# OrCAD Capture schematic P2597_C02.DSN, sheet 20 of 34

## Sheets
20 14_HDMI: size Custom
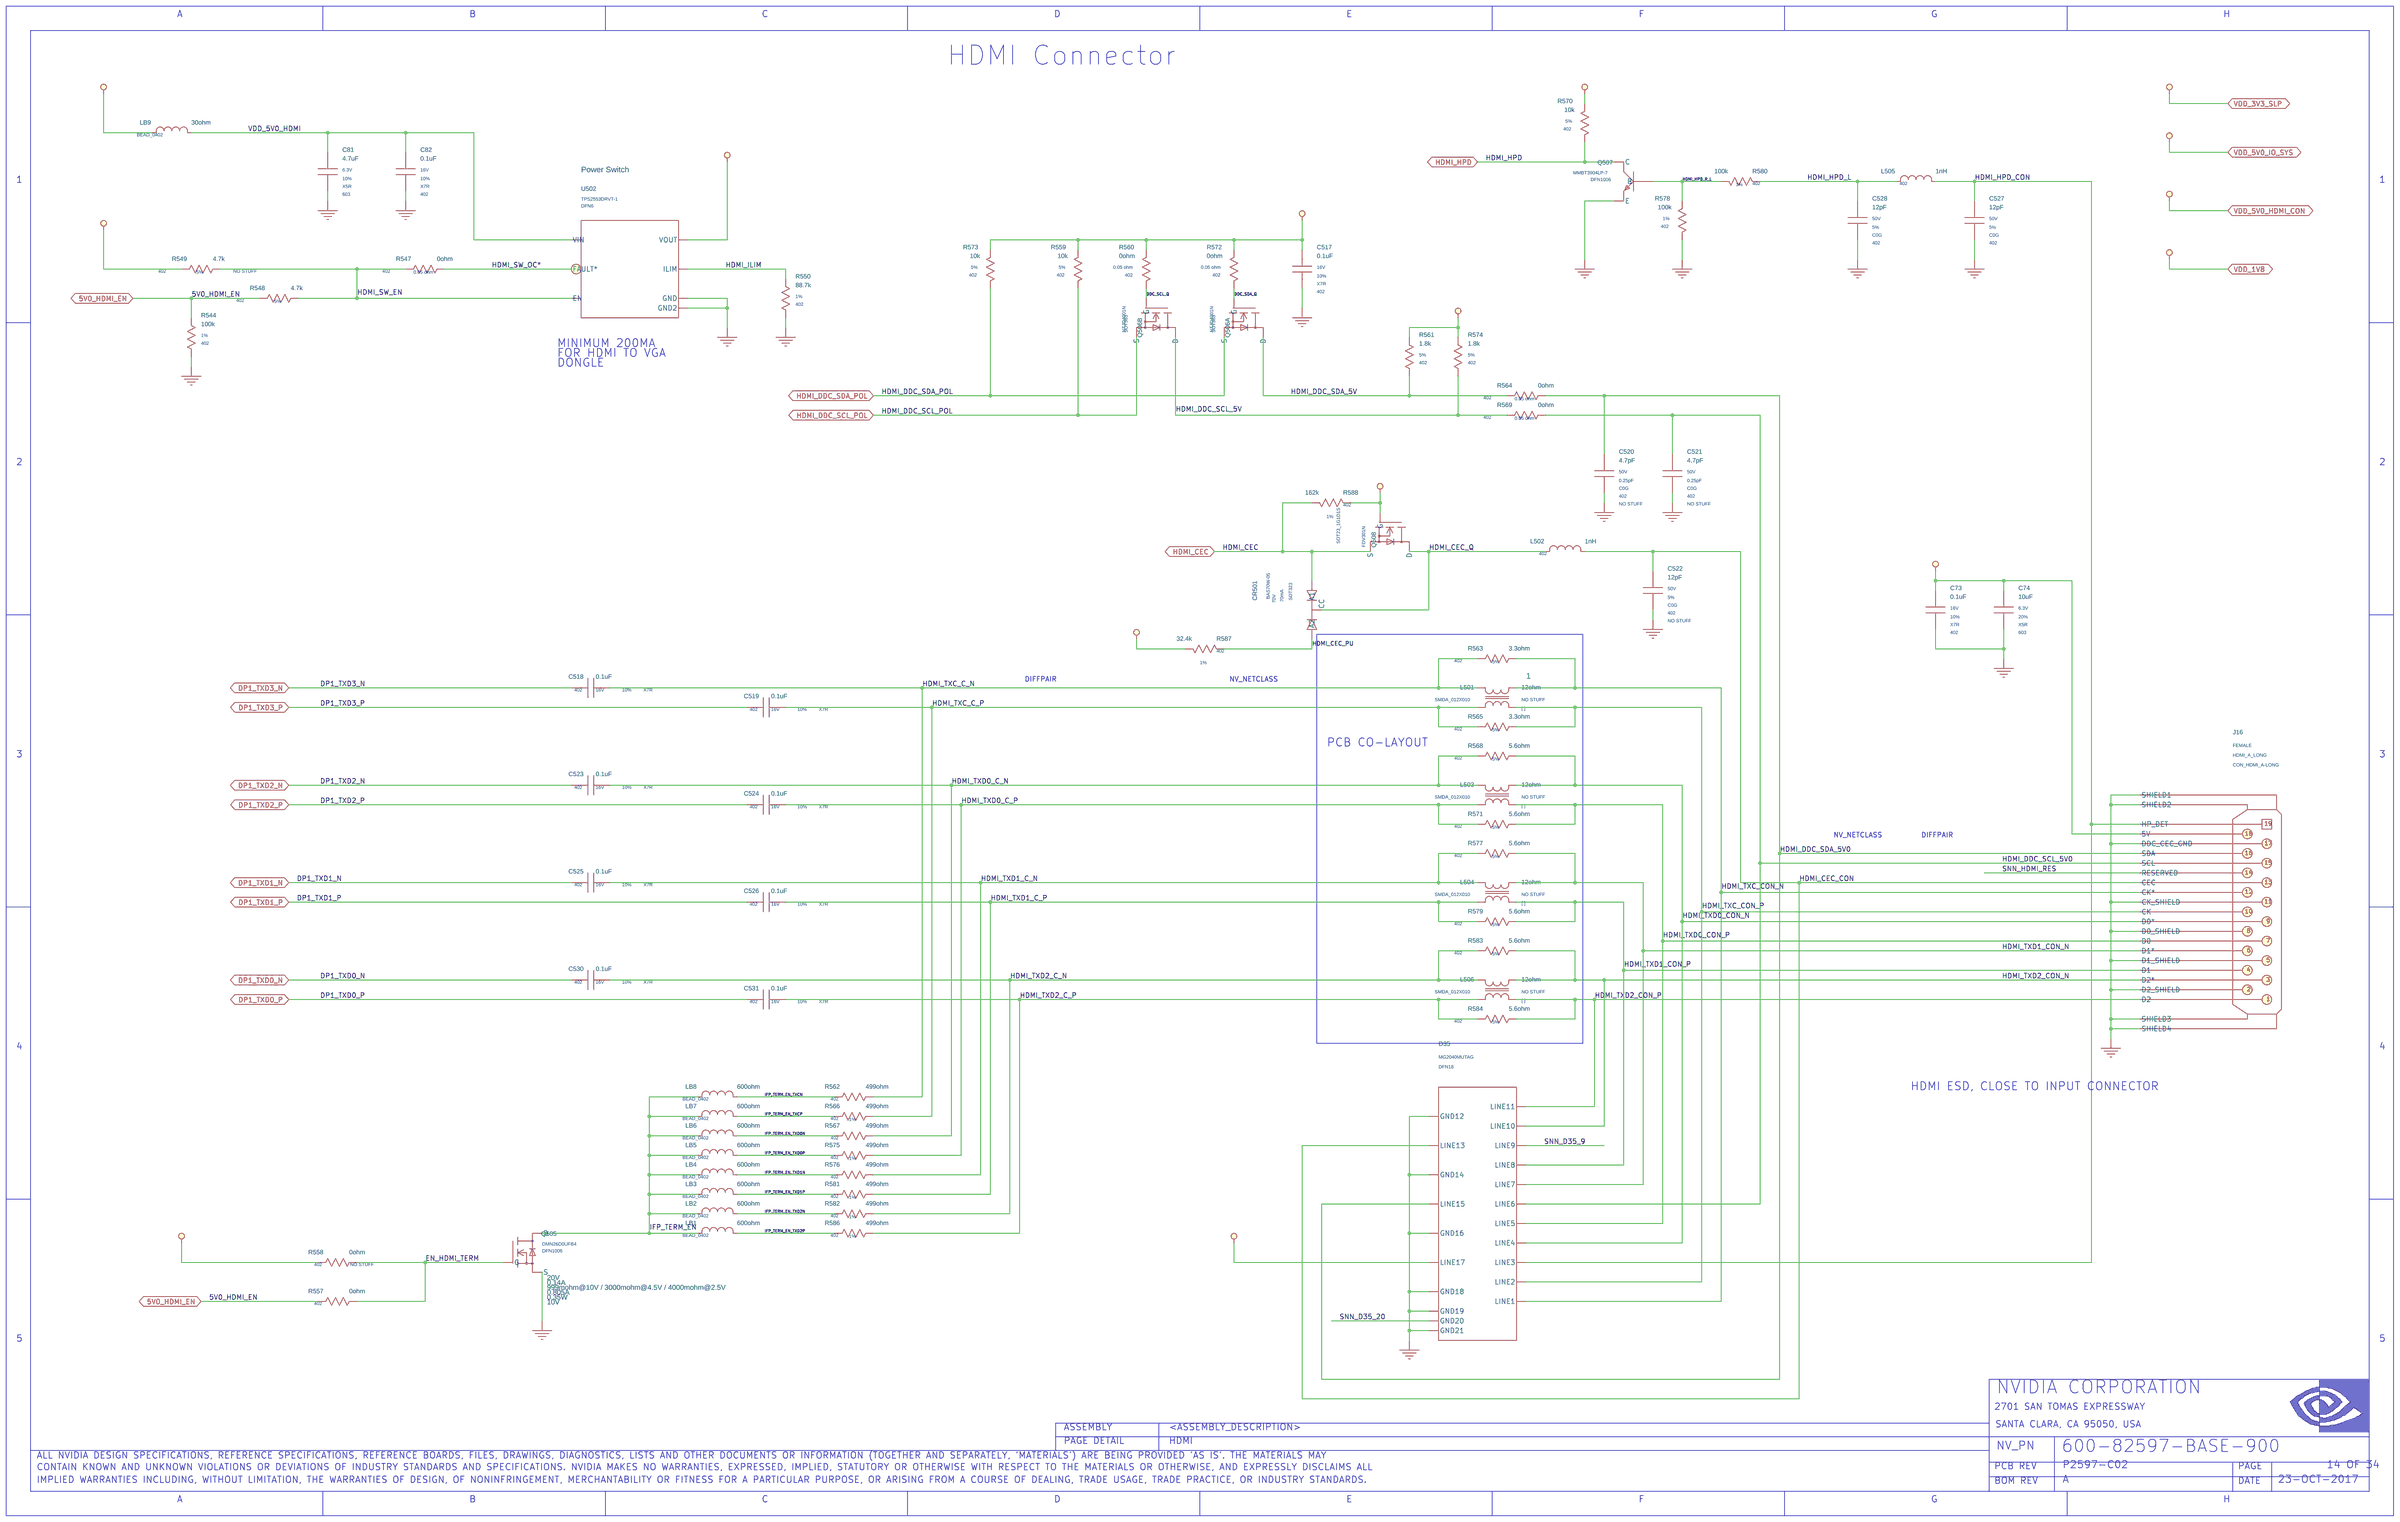
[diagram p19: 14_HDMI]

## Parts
C73  0.1uF  [402]
C74  10uF  [603]
C81  4.7uF  [603]
C82  0.1uF  [402]
C517  0.1uF  [402]
C518  0.1uF  [402]
C519  0.1uF  [402]
C520  4.7pF  [402]
C521  4.7pF  [402]
C522  12pF  [402]
C523  0.1uF  [402]
C524  0.1uF  [402]
C525  0.1uF  [402]
C526  0.1uF  [402]
C527  12pF  [402]
C528  12pF  [402]
C530  0.1uF  [402]
C531  0.1uF  [402]
CR501  D_3PIN_CC  [SOT323]
D35  D_ESD  [DFN18_P050_055X015_3XT006X005]
J16  CON_HDMI  [CON_HDMI_019_SMD_RA_F_C]
L501  12ohm  [IND_NONRKO_SMD_012X010]
L502  1nH  [IND_SMD_0402]
L503  12ohm  [IND_NONRKO_SMD_012X010]
L504  12ohm  [IND_NONRKO_SMD_012X010]
L505  1nH  [IND_SMD_0402]
L506  12ohm  [IND_NONRKO_SMD_012X010]
LB1  600ohm  [IND_SMD_0402]
LB2  600ohm  [IND_SMD_0402]
LB3  600ohm  [IND_SMD_0402]
LB4  600ohm  [IND_SMD_0402]
LB5  600ohm  [IND_SMD_0402]
LB6  600ohm  [IND_SMD_0402]
LB7  600ohm  [IND_SMD_0402]
LB8  600ohm  [IND_SMD_0402]
LB9  30ohm  [IND_SMD_0402]
Q505  Q_FET_N_ENH  [DFET_003_SMD_010X006_B]
Q506  Q_FET_N_ENH  [SC70_6]  (sections A,B)
Q507  Q_NPN  [DFET_003_SMD_010X006_B]
Q508  Q_FET_N_ENH  [SOT23]
R544  100k  [402]
R547  0ohm  [402]
R548  4.7k  [402]
R549  4.7k  [402]
R550  88.7k  [402]
R557  0ohm  [402]
R558  0ohm  [402]
R559  10k  [402]
R560  0ohm  [402]
R561  1.8k  [402]
R562  499ohm  [402]
R563  3.3ohm  [402]
R564  0ohm  [402]
R565  3.3ohm  [402]
R566  499ohm  [402]
R567  499ohm  [402]
R568  5.6ohm  [402]
R569  0ohm  [402]
R570  10k  [402]
R571  5.6ohm  [402]
R572  0ohm  [402]
R573  10k  [402]
R574  1.8k  [402]
R575  499ohm  [402]
R576  499ohm  [402]
R577  5.6ohm  [402]
R578  100k  [402]
R579  5.6ohm  [402]
R580  100k  [402]
R581  499ohm  [402]
R582  499ohm  [402]
R583  5.6ohm  [402]
R584  5.6ohm  [402]
R586  499ohm  [402]
R587  32.4k  [402]
R588  162k  [402]
U502  U_POWER_SW  [DFN06_P065_020X020_T016X010]

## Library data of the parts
C73 = C: ASSEMBLY: HDMI; CDS_LIB: discrete; CDS_PART_NAME: C_0402-0.1UF,X7R,10%,16V,036-0014-000; CDS_PHYS_PART_NAME: C_0402-0.1UF,X7R,10%,16V,036-0014-000-0.1UF,036-0014-000; CDS_SEC: 1; DEVICE_TYPENAME: C_0402-01UFX7R1016V036-0014-000-01UF036-0014-000; DRAWING: @P2597_C02_LIB.P2597_C02(SCH_1):PAGE14; ESL: N/A; ESR: N/A; MAT: X7R; MAX_VOLTAGE: 16V; NV_PN: 036-0014-000; PATH: I332; PHYS_PAGE: 14; ROT: 0; SEC: 1; SIGNAL_MODEL: nv_cap; TOL: 10%; VER: 1; XY: (-2250,4500)
C74 = C: ASSEMBLY: HDMI; CDS_LIB: discrete; CDS_PART_NAME: C_0603-10UF,X5R,20%,6.3V,039-0135-000; CDS_PHYS_PART_NAME: C_0603-10UF,X5R,20%,6.3V,039-0135-000-039-0135-000,10UF; CDS_SEC: 1; DEVICE_TYPENAME: C_0603-10UFX5R2063V039-0135-000-039-0135-00010UF; DRAWING: @P2597_C02_LIB.P2597_C02(SCH_1):PAGE14; ESL: N/A; ESR: N/A; MAT: X5R; MAX_VOLTAGE: 6.3V; NV_PN: 039-0135-000; PATH: I340; PHYS_PAGE: 14; ROT: 0; SEC: 1; SIGNAL_MODEL: nv_cap; TOL: 20%; VER: 1; XY: (-1900,4500)
C81 = C: ASSEMBLY: HDMI; CDS_LIB: discrete; CDS_PART_NAME: C_0603-4.7UF,X5R,10%,6.3V,039-0037-000; CDS_PHYS_PART_NAME: C_0603-4.7UF,X5R,10%,6.3V,039-0037-000-039-0037-000,4.7UF; CDS_SEC: 1; DEVICE_TYPENAME: C_0603-47UFX5R1063V039-0037-000-039-0037-00047UF; DRAWING: @P2597_C02_LIB.P2597_C02(SCH_1):PAGE14; MAT: X5R; MAX_VOLTAGE: 6.3V; NV_PN: 039-0037-000; PATH: I266; PHYS_PAGE: 14; ROT: 0; SEC: 1; SIGNAL_MODEL: nv_cap; TOL: 10%; VER: 1; XY: (-10500,6750)
C82 = C: ASSEMBLY: HDMI; CDS_LIB: discrete; CDS_PART_NAME: C_0402-0.1UF,X7R,10%,16V,036-0014-000; CDS_PHYS_PART_NAME: C_0402-0.1UF,X7R,10%,16V,036-0014-000-0.1UF,036-0014-000; CDS_SEC: 1; DEVICE_TYPENAME: C_0402-01UFX7R1016V036-0014-000-01UF036-0014-000; DRAWING: @P2597_C02_LIB.P2597_C02(SCH_1):PAGE14; ESL: N/A; ESR: N/A; MAT: X7R; MAX_VOLTAGE: 16V; NV_PN: 036-0014-000; PATH: I271; PHYS_PAGE: 14; ROT: 0; SEC: 1; SIGNAL_MODEL: nv_cap; TOL: 10%; VER: 1; XY: (-10100,6750)
C517 = C: ASSEMBLY: HDMI; CDS_LIB: discrete; CDS_PART_NAME: C_0402-0.1UF,X7R,10%,16V,036-0014-000; CDS_PHYS_PART_NAME: C_0402-0.1UF,X7R,10%,16V,036-0014-000-0.1UF,036-0014-000; CDS_SEC: 1; DEVICE_TYPENAME: C_0402-01UFX7R1016V036-0014-000-01UF036-0014-000; DRAWING: @P2597_C02_LIB.P2597_C02(SCH_1):PAGE14; ESL: N/A; ESR: N/A; MAT: X7R; MAX_VOLTAGE: 16V; NV_PN: 036-0014-000; PATH: I315; PHYS_PAGE: 14; ROT: 0; SEC: 1; SIGNAL_MODEL: nv_cap; TOL: 10%; VER: 1; XY: (-5500,6250)
C518 = C#1: ASSEMBLY: IO_HDMI; CDS_LIB: discrete; CDS_PART_NAME: C_0402-0.1UF,X7R,10%,16V,036-0014-000; CDS_PHYS_PART_NAME: C_0402-0.1UF,X7R,10%,16V,036-0014-000-0.1UF,036-0014-000; CDS_SEC: 1; CHIPS_PART_NAME: C; DEVICE_TYPENAME: C_0402-01UFX7R1016V036-0014-000-01UF036-0014-000; DRAWING: @P2597_C02_LIB.P2597_C02(SCH_1):PAGE14; MAT: X7R; MAX_VOLTAGE: 16V; NO_XNET: 1; NV_PN: 036-0014-000; PATH: I259; PHYS_PAGE: 14; ROT: 0; SEC: 1; SIGNAL_MODEL: nv_cap; TOL: 10%; VER: 2; XY: (-9150,4100)
C519 = C#1: ASSEMBLY: IO_HDMI; CDS_LIB: discrete; CDS_PART_NAME: C_0402-0.1UF,X7R,10%,16V,036-0014-000; CDS_PHYS_PART_NAME: C_0402-0.1UF,X7R,10%,16V,036-0014-000-0.1UF,036-0014-000; CDS_SEC: 1; CHIPS_PART_NAME: C; DEVICE_TYPENAME: C_0402-01UFX7R1016V036-0014-000-01UF036-0014-000; DRAWING: @P2597_C02_LIB.P2597_C02(SCH_1):PAGE14; MAT: X7R; MAX_VOLTAGE: 16V; NO_XNET: 1; NV_PN: 036-0014-000; PATH: I260; PHYS_PAGE: 14; ROT: 0; SEC: 1; SIGNAL_MODEL: nv_cap; TOL: 10%; VER: 2; XY: (-8250,4000)
C520 = C: ASSEMBLY: HDMI; CDS_LIB: discrete; CDS_PART_NAME: C_0402-4.7PF,C0G,0.25PF,50V,035-0031-000; CDS_PHYS_PART_NAME: C_0402-4.7PF,C0G,0.25PF,50V,035-0031-000-035-0031-000,4.7PF; CDS_SEC: 1; DEVICE_TYPENAME: C_0402-47PFC0G025PF50V035-0031-000-035-0031-00047PF; DRAWING: @P2597_C02_LIB.P2597_C02(SCH_1):PAGE14; MAT: C0G; MAX_VOLTAGE: 50V; NV_PN: 035-0031-000; PATH: I342; PHYS_PAGE: 14; ROT: 0; SEC: 1; SIGNAL_MODEL: nv_cap; SKU: NO STUFF; TOL: 0.25pF; VER: 1; XY: (-3950,5200)
C521 = C: ASSEMBLY: HDMI; CDS_LIB: discrete; CDS_PART_NAME: C_0402-4.7PF,C0G,0.25PF,50V,035-0031-000; CDS_PHYS_PART_NAME: C_0402-4.7PF,C0G,0.25PF,50V,035-0031-000-035-0031-000,4.7PF; CDS_SEC: 1; DEVICE_TYPENAME: C_0402-47PFC0G025PF50V035-0031-000-035-0031-00047PF; DRAWING: @P2597_C02_LIB.P2597_C02(SCH_1):PAGE14; MAT: C0G; MAX_VOLTAGE: 50V; NV_PN: 035-0031-000; PATH: I344; PHYS_PAGE: 14; ROT: 0; SEC: 1; SIGNAL_MODEL: nv_cap; SKU: NO STUFF; TOL: 0.25pF; VER: 1; XY: (-3600,5200)
C522 = C: ASSEMBLY: HDMI; CDS_LIB: discrete; CDS_PART_NAME: C_0402-12PF,C0G,5%,50V,035-0014-000; CDS_PHYS_PART_NAME: C_0402-12PF,C0G,5%,50V,035-0014-000-035-0014-000,12PF; CDS_SEC: 1; DEVICE_TYPENAME: C_0402-12PFC0G550V035-0014-000-035-0014-00012PF; DRAWING: @P2597_C02_LIB.P2597_C02(SCH_1):PAGE14; ESL: N/A; ESR: N/A; MAT: C0G; MAX_VOLTAGE: 50V; NV_PN: 035-0014-000; PATH: I330; PHYS_PAGE: 14; ROT: 0; SEC: 1; SIGNAL_MODEL: nv_cap; SKU: NO STUFF; TOL: 5%; VER: 1; XY: (-3700,4600)
C523 = C#1: ASSEMBLY: IO_HDMI; CDS_LIB: discrete; CDS_PART_NAME: C_0402-0.1UF,X7R,10%,16V,036-0014-000; CDS_PHYS_PART_NAME: C_0402-0.1UF,X7R,10%,16V,036-0014-000-0.1UF,036-0014-000; CDS_SEC: 1; CHIPS_PART_NAME: C; DEVICE_TYPENAME: C_0402-01UFX7R1016V036-0014-000-01UF036-0014-000; DRAWING: @P2597_C02_LIB.P2597_C02(SCH_1):PAGE14; MAT: X7R; MAX_VOLTAGE: 16V; NO_XNET: 1; NV_PN: 036-0014-000; PATH: I258; PHYS_PAGE: 14; ROT: 0; SEC: 1; SIGNAL_MODEL: nv_cap; TOL: 10%; VER: 2; XY: (-9150,3600)
C524 = C#1: ASSEMBLY: IO_HDMI; CDS_LIB: discrete; CDS_PART_NAME: C_0402-0.1UF,X7R,10%,16V,036-0014-000; CDS_PHYS_PART_NAME: C_0402-0.1UF,X7R,10%,16V,036-0014-000-0.1UF,036-0014-000; CDS_SEC: 1; CHIPS_PART_NAME: C; DEVICE_TYPENAME: C_0402-01UFX7R1016V036-0014-000-01UF036-0014-000; DRAWING: @P2597_C02_LIB.P2597_C02(SCH_1):PAGE14; MAT: X7R; MAX_VOLTAGE: 16V; NO_XNET: 1; NV_PN: 036-0014-000; PATH: I255; PHYS_PAGE: 14; ROT: 0; SEC: 1; SIGNAL_MODEL: nv_cap; TOL: 10%; VER: 2; XY: (-8250,3500)
C525 = C#1: ASSEMBLY: IO_HDMI; CDS_LIB: discrete; CDS_PART_NAME: C_0402-0.1UF,X7R,10%,16V,036-0014-000; CDS_PHYS_PART_NAME: C_0402-0.1UF,X7R,10%,16V,036-0014-000-0.1UF,036-0014-000; CDS_SEC: 1; CHIPS_PART_NAME: C; DEVICE_TYPENAME: C_0402-01UFX7R1016V036-0014-000-01UF036-0014-000; DRAWING: @P2597_C02_LIB.P2597_C02(SCH_1):PAGE14; MAT: X7R; MAX_VOLTAGE: 16V; NO_XNET: 1; NV_PN: 036-0014-000; PATH: I254; PHYS_PAGE: 14; ROT: 0; SEC: 1; SIGNAL_MODEL: nv_cap; TOL: 10%; VER: 2; XY: (-9150,3100)
C526 = C#1: ASSEMBLY: IO_HDMI; CDS_LIB: discrete; CDS_PART_NAME: C_0402-0.1UF,X7R,10%,16V,036-0014-000; CDS_PHYS_PART_NAME: C_0402-0.1UF,X7R,10%,16V,036-0014-000-0.1UF,036-0014-000; CDS_SEC: 1; CHIPS_PART_NAME: C; DEVICE_TYPENAME: C_0402-01UFX7R1016V036-0014-000-01UF036-0014-000; DRAWING: @P2597_C02_LIB.P2597_C02(SCH_1):PAGE14; MAT: X7R; MAX_VOLTAGE: 16V; NO_XNET: 1; NV_PN: 036-0014-000; PATH: I256; PHYS_PAGE: 14; ROT: 0; SEC: 1; SIGNAL_MODEL: nv_cap; TOL: 10%; VER: 2; XY: (-8250,3000)
C527 = C: ASSEMBLY: HDMI; CDS_LIB: discrete; CDS_PART_NAME: C_0402-12PF,C0G,5%,50V,035-0014-000; CDS_PHYS_PART_NAME: C_0402-12PF,C0G,5%,50V,035-0014-000-035-0014-000,12PF; CDS_SEC: 1; DEVICE_TYPENAME: C_0402-12PFC0G550V035-0014-000-035-0014-00012PF; DRAWING: @P2597_C02_LIB.P2597_C02(SCH_1):PAGE14; ESL: N/A; ESR: N/A; MAT: C0G; MAX_VOLTAGE: 50V; NV_PN: 035-0014-000; PATH: I357; PHYS_PAGE: 14; ROT: 0; SEC: 1; SIGNAL_MODEL: nv_cap; TOL: 5%; VER: 1; XY: (-2050,6500)
C528 = C: ASSEMBLY: HDMI; CDS_LIB: discrete; CDS_PART_NAME: C_0402-12PF,C0G,5%,50V,035-0014-000; CDS_PHYS_PART_NAME: C_0402-12PF,C0G,5%,50V,035-0014-000-035-0014-000,12PF; CDS_SEC: 1; DEVICE_TYPENAME: C_0402-12PFC0G550V035-0014-000-035-0014-00012PF; DRAWING: @P2597_C02_LIB.P2597_C02(SCH_1):PAGE14; ESL: N/A; ESR: N/A; MAT: C0G; MAX_VOLTAGE: 50V; NV_PN: 035-0014-000; PATH: I350; PHYS_PAGE: 14; ROT: 0; SEC: 1; SIGNAL_MODEL: nv_cap; TOL: 5%; VER: 1; XY: (-2650,6500)
C530 = C#1: ASSEMBLY: IO_HDMI; CDS_LIB: discrete; CDS_PART_NAME: C_0402-0.1UF,X7R,10%,16V,036-0014-000; CDS_PHYS_PART_NAME: C_0402-0.1UF,X7R,10%,16V,036-0014-000-0.1UF,036-0014-000; CDS_SEC: 1; CHIPS_PART_NAME: C; DEVICE_TYPENAME: C_0402-01UFX7R1016V036-0014-000-01UF036-0014-000; DRAWING: @P2597_C02_LIB.P2597_C02(SCH_1):PAGE14; MAT: X7R; MAX_VOLTAGE: 16V; NO_XNET: 1; NV_PN: 036-0014-000; PATH: I253; PHYS_PAGE: 14; ROT: 0; SEC: 1; SIGNAL_MODEL: nv_cap; TOL: 10%; VER: 2; XY: (-9150,2600)
C531 = C#1: ASSEMBLY: IO_HDMI; CDS_LIB: discrete; CDS_PART_NAME: C_0402-0.1UF,X7R,10%,16V,036-0014-000; CDS_PHYS_PART_NAME: C_0402-0.1UF,X7R,10%,16V,036-0014-000-0.1UF,036-0014-000; CDS_SEC: 1; CHIPS_PART_NAME: C; DEVICE_TYPENAME: C_0402-01UFX7R1016V036-0014-000-01UF036-0014-000; DRAWING: @P2597_C02_LIB.P2597_C02(SCH_1):PAGE14; MAT: X7R; MAX_VOLTAGE: 16V; NO_XNET: 1; NV_PN: 036-0014-000; PATH: I257; PHYS_PAGE: 14; ROT: 0; SEC: 1; SIGNAL_MODEL: nv_cap; TOL: 10%; VER: 2; XY: (-8250,2500)
CR501 = D_3PIN_CC#1: ASSEMBLY: HDMI; CDS_LIB: discrete; CDS_PART_NAME: D_3PIN_CC_SOT323-BAS70W-05,1 PAIR - COMMON CATHODE,70V,0.1A,1V@15MA,70MA,091-0023-000; CDS_PHYS_PART_NAME: D_3PIN_CC_SOT323-BAS70W-05,1 PAIR - COMMON CATHODE,70V,0.1A,1V@15MA,70MA,091-0023-000-091-0023-000; CDS_SEC: 1; CONFIGURATION: 1 Pair - Common Cathode; CONTINUOUS_CURRENT: 70mA; DEVICE_TYPENAME: D_3PIN_CC_SOT323-BAS70W-051PAIR-COMMONCATHODE70V01A1V15MA70MA091-0023-000-091-0023-000; DRAWING: @P2597_C02_LIB.P2597_C02(SCH_1):PAGE14; FORWARD_VOLTAGE: 1V@15mA; MAX_CURRENT: 0.1A; MAX_VOLTAGE: 70V; NV_NAME: BAS70W-05; NV_PN: 091-0023-000; PATH: I291; PHYS_PAGE: 14; ROT: 1; SEC: 1; VER: 4; XY: (-5450,4500)
D35 = D_ESD#2: ASSEMBLY: HDMI; BREAKDOWN_VOLTAGE_MIN_TYP: 5.5V; CAPACITANCE_MAX_TYP: 0.42pF; CDS_LIB: discrete; CDS_PART_NAME: D_ESD_DFN18-MG2040MUTAG,OTHER,UNI-DIRECTIONAL,5V,1UA,5.5V,11.4V@8A,0.42PF,091-0080-000; CDS_PHYS_PART_NAME: D_ESD_DFN18-MG2040MUTAG,OTHER,UNI-DIRECTIONAL,5V,1UA,5.5V,11.4V@8A,0.42PF,091-0080-000-091-0080-000; CDS_SEC: 1; CLAMPING_VOLTAGE: 11.4V@8A; CONFIGURATION: Other; DEVICE_TYPENAME: D_ESD_DFN18-MG2040MUTAGOTHERUNI-DIRECTIONAL5V1UA55V114V8A042PF091-0080-000-091-0080-000; DRAWING: @P2597_C02_LIB.P2597_C02(SCH_1):PAGE14; MAX_REVERSE_LEAKAGE_CURRENT: 1uA; MAX_REVERSE_VOLTAGE: 5V; NV_NAME: MG2040MUTAG; NV_PN: 091-0080-000; PACK_TYPE: DFN18; PATH: I381; PHYS_PAGE: 14; POLARITY: Uni-Directional; ROT: 0; SEC: 1; SEC_TYPE: DFN18; VER: 7; XY: (-4600,1450)
J16 = CON_HDMI: ANGLE: 90; ASSEMBLY: HDMI; CDS_LIB: electro_mechanic; CDS_PART_NAME: CON_HDMI_HDMI_A_LONG-CON_HDMI_A-LONG,FEMALE,0.5MM,90,YES,N/A,N/A,YES,YES,N/A,N/A,080-0420-000; CDS_PHYS_PART_NAME: CON_HDMI_HDMI_A_LONG-CON_HDMI_A-LONG,FEMALE,0.5MM,90,YES,N/A,N/A,YES,YES,N/A,N/A,080-0420-000-080-0420-000; CDS_SEC: 1; DEVICE_TYPENAME: CON_HDMI_HDMI_A_LONG-CON_HDMI_A-LONGFEMALE05MM90YESNANAYESYESNANA080-0420-000-080-0420-000; DRAWING: @P2597_C02_LIB.P2597_C02(SCH_1):PAGE14; EMI_GROUND_TAB: YES; GENDER: FEMALE; LATCHING: N/A; MAX_CURRENT: N/A; MAX_VOLTAGE: N/A; NV_NAME: CON_HDMI_A-LONG; NV_PN: 080-0420-000; PACK_TYPE: HDMI_A_LONG; PATH: I338; PHYS_PAGE: 14; PITCH: 0.5MM; REFLOW: YES; ROT: 0; SEC: 1; SEC_TYPE: HDMI_A_LONG; SHIELDED: YES; SHROUDED: N/A; VER: 1; XY: (-600,2950)
L501 = L_CMF_4P: ASSEMBLY: HDMI; CDS_LIB: discrete; CDS_PART_NAME: L_CMF_4P_SMDA_012X010-12OHM,[ ],[ ],0.1A,0.7OHM,[ ],102-0015-000; CDS_PHYS_PART_NAME: L_CMF_4P_SMDA_012X010-12OHM,[ ],[ ],0.1A,0.7OHM,[ ],102-0015-000-102-0015-000,12OHM; CDS_SEC: 1; DC_RESISTANCE: 0.7ohm; DEVICE_TYPENAME: L_CMF_4P_SMDA_012X010-12OHM01A07OHM102-0015-000-102-0015-00012OHM; DRAWING: @P2597_C02_LIB.P2597_C02(SCH_1):PAGE14; MAT: [ ]; MAX_CURRENT: 0.1A; NO_XNET_CONNECTION: 1; NV_NAME: [ ]; NV_PN: 102-0015-000; PACK_TYPE: SMDA_012X010; PATH: I301; PHYS_PAGE: 14; PLACEMENT_NOTE: CoLayout with R563, R565; ROT: 0; SEC: 1; SEC_TYPE: SMDA_012X010; SIGNAL_MODEL: nv_ind_cmf_4p; SKU: NO STUFF; TOL: [ ]; VER: 1; XY: (-4500,4050)
L502 = L: ACOUSTIC_MARGIN: [ ]; ASSEMBLY: HDMI; CDS_LIB: discrete; CDS_PART_NAME: L_0402-1NH,MULTI-LAYER,30%,0.4A,0.4A,0.07OHM,8@100MHZ,10GHZ,[ ],130-1041-000; CDS_PHYS_PART_NAME: L_0402-1NH,MULTI-LAYER,30%,0.4A,0.4A,0.07OHM,8@100MHZ,10GHZ,[ ],130-1041-000-130-1041-000,1NH; CDS_SEC: 1; CONTINUOUS_CURRENT: 0.4A; DC_RESISTANCE: 0.07ohm; DEVICE_TYPENAME: L_0402-1NHMULTI-LAYER3004A04A007OHM8100MHZ10GHZ130-1041-000-130-1041-0001NH; DRAWING: @P2597_C02_LIB.P2597_C02(SCH_1):PAGE14; MAT: multi-layer; MAX_CURRENT: 0.4A; NV_PN: 130-1041-000; PACK_TYPE: 402; PATH: I319; PHYS_PAGE: 14; Q: 8@100MHz; ROT: 0; SEC: 1; SELF_RESONANCE_FREQ: 10GHz; SIGNAL_MODEL: nv_ind; TOL: 30%; VER: 1; XY: (-4150,4800)
L503 = L_CMF_4P: ASSEMBLY: HDMI; CDS_LIB: discrete; CDS_PART_NAME: L_CMF_4P_SMDA_012X010-12OHM,[ ],[ ],0.1A,0.7OHM,[ ],102-0015-000; CDS_PHYS_PART_NAME: L_CMF_4P_SMDA_012X010-12OHM,[ ],[ ],0.1A,0.7OHM,[ ],102-0015-000-102-0015-000,12OHM; CDS_SEC: 1; DC_RESISTANCE: 0.7ohm; DEVICE_TYPENAME: L_CMF_4P_SMDA_012X010-12OHM01A07OHM102-0015-000-102-0015-00012OHM; DRAWING: @P2597_C02_LIB.P2597_C02(SCH_1):PAGE14; MAT: [ ]; MAX_CURRENT: 0.1A; NV_NAME: [ ]; NV_PN: 102-0015-000; PACK_TYPE: SMDA_012X010; PATH: I298; PHYS_PAGE: 14; PLACEMENT_NOTE: CoLayout with R568, R571; ROT: 0; SEC: 1; SEC_TYPE: SMDA_012X010; SIGNAL_MODEL: nv_ind_cmf_4p; SKU: NO STUFF; TOL: [ ]; VER: 1; XY: (-4500,3550)
L504 = L_CMF_4P: ASSEMBLY: HDMI; CDS_LIB: discrete; CDS_PART_NAME: L_CMF_4P_SMDA_012X010-12OHM,[ ],[ ],0.1A,0.7OHM,[ ],102-0015-000; CDS_PHYS_PART_NAME: L_CMF_4P_SMDA_012X010-12OHM,[ ],[ ],0.1A,0.7OHM,[ ],102-0015-000-102-0015-000,12OHM; CDS_SEC: 1; DC_RESISTANCE: 0.7ohm; DEVICE_TYPENAME: L_CMF_4P_SMDA_012X010-12OHM01A07OHM102-0015-000-102-0015-00012OHM; DRAWING: @P2597_C02_LIB.P2597_C02(SCH_1):PAGE14; MAT: [ ]; MAX_CURRENT: 0.1A; NV_NAME: [ ]; NV_PN: 102-0015-000; PACK_TYPE: SMDA_012X010; PATH: I295; PHYS_PAGE: 14; PLACEMENT_NOTE: CoLayout with R577, R579; ROT: 0; SEC: 1; SEC_TYPE: SMDA_012X010; SIGNAL_MODEL: nv_ind_cmf_4p; SKU: NO STUFF; TOL: [ ]; VER: 1; XY: (-4500,3050)
L505 = L: ACOUSTIC_MARGIN: [ ]; ASSEMBLY: HDMI; CDS_LIB: discrete; CDS_PART_NAME: L_0402-1NH,MULTI-LAYER,30%,0.4A,0.4A,0.07OHM,8@100MHZ,10GHZ,[ ],130-1041-000; CDS_PHYS_PART_NAME: L_0402-1NH,MULTI-LAYER,30%,0.4A,0.4A,0.07OHM,8@100MHZ,10GHZ,[ ],130-1041-000-130-1041-000,1NH; CDS_SEC: 1; CONTINUOUS_CURRENT: 0.4A; DC_RESISTANCE: 0.07ohm; DEVICE_TYPENAME: L_0402-1NHMULTI-LAYER3004A04A007OHM8100MHZ10GHZ130-1041-000-130-1041-0001NH; DRAWING: @P2597_C02_LIB.P2597_C02(SCH_1):PAGE14; MAT: multi-layer; MAX_CURRENT: 0.4A; NV_PN: 130-1041-000; PACK_TYPE: 402; PATH: I355; PHYS_PAGE: 14; Q: 8@100MHz; ROT: 0; SEC: 1; SELF_RESONANCE_FREQ: 10GHz; SIGNAL_MODEL: nv_ind; TOL: 30%; VER: 1; XY: (-2350,6700)
L506 = L_CMF_4P: ASSEMBLY: HDMI; CDS_LIB: discrete; CDS_PART_NAME: L_CMF_4P_SMDA_012X010-12OHM,[ ],[ ],0.1A,0.7OHM,[ ],102-0015-000; CDS_PHYS_PART_NAME: L_CMF_4P_SMDA_012X010-12OHM,[ ],[ ],0.1A,0.7OHM,[ ],102-0015-000-102-0015-000,12OHM; CDS_SEC: 1; DC_RESISTANCE: 0.7ohm; DEVICE_TYPENAME: L_CMF_4P_SMDA_012X010-12OHM01A07OHM102-0015-000-102-0015-00012OHM; DRAWING: @P2597_C02_LIB.P2597_C02(SCH_1):PAGE14; MAT: [ ]; MAX_CURRENT: 0.1A; NV_NAME: [ ]; NV_PN: 102-0015-000; PACK_TYPE: SMDA_012X010; PATH: I293; PHYS_PAGE: 14; PLACEMENT_NOTE: CoLayout with R583, R584; ROT: 0; SEC: 1; SEC_TYPE: SMDA_012X010; SIGNAL_MODEL: nv_ind_cmf_4p; SKU: NO STUFF; TOL: [ ]; VER: 1; XY: (-4500,2550)
LB1 = L: ACOUSTIC_MARGIN: N/A; ASSEMBLY: HDMI; CDS_LIB: discrete; CDS_PART_NAME: L_BEAD_0402-600OHM,FERRITE,25%,0.5A,0.5A,0.39OHM,[ ],N/A,N/A,100-0183-000; CDS_PHYS_PART_NAME: L_BEAD_0402-600OHM,FERRITE,25%,0.5A,0.5A,0.39OHM,[ ],N/A,N/A,100-0183-000-100-0183-000,600OHM; CDS_SEC: 1; CONTINUOUS_CURRENT: 0.5A; DC_RESISTANCE: 0.39ohm; DEVICE_TYPENAME: L_BEAD_0402-600OHMFERRITE2505A05A039OHMNANA100-0183-000-100-0183-000600OHM; DRAWING: @P2597_C02_LIB.P2597_C02(SCH_1):PAGE14; MAT: Ferrite; MAX_CURRENT: 0.5A; NV_PN: 100-0183-000; PACK_TYPE: BEAD_0402; PATH: I363; PHYS_PAGE: 14; Q: [ ]; ROT: 0; SEC: 1; SELF_RESONANCE_FREQ: N/A; SIGNAL_MODEL: nv_ind_noxnet; TOL: 25%; VER: 1; XY: (-8500,1300)
LB2 = L: ACOUSTIC_MARGIN: N/A; ASSEMBLY: HDMI; CDS_LIB: discrete; CDS_PART_NAME: L_BEAD_0402-600OHM,FERRITE,25%,0.5A,0.5A,0.39OHM,[ ],N/A,N/A,100-0183-000; CDS_PHYS_PART_NAME: L_BEAD_0402-600OHM,FERRITE,25%,0.5A,0.5A,0.39OHM,[ ],N/A,N/A,100-0183-000-100-0183-000,600OHM; CDS_SEC: 1; CONTINUOUS_CURRENT: 0.5A; DC_RESISTANCE: 0.39ohm; DEVICE_TYPENAME: L_BEAD_0402-600OHMFERRITE2505A05A039OHMNANA100-0183-000-100-0183-000600OHM; DRAWING: @P2597_C02_LIB.P2597_C02(SCH_1):PAGE14; MAT: Ferrite; MAX_CURRENT: 0.5A; NV_PN: 100-0183-000; PACK_TYPE: BEAD_0402; PATH: I364; PHYS_PAGE: 14; Q: [ ]; ROT: 0; SEC: 1; SELF_RESONANCE_FREQ: N/A; SIGNAL_MODEL: nv_ind_noxnet; TOL: 25%; VER: 1; XY: (-8500,1400)
LB3 = L: ACOUSTIC_MARGIN: N/A; ASSEMBLY: HDMI; CDS_LIB: discrete; CDS_PART_NAME: L_BEAD_0402-600OHM,FERRITE,25%,0.5A,0.5A,0.39OHM,[ ],N/A,N/A,100-0183-000; CDS_PHYS_PART_NAME: L_BEAD_0402-600OHM,FERRITE,25%,0.5A,0.5A,0.39OHM,[ ],N/A,N/A,100-0183-000-100-0183-000,600OHM; CDS_SEC: 1; CONTINUOUS_CURRENT: 0.5A; DC_RESISTANCE: 0.39ohm; DEVICE_TYPENAME: L_BEAD_0402-600OHMFERRITE2505A05A039OHMNANA100-0183-000-100-0183-000600OHM; DRAWING: @P2597_C02_LIB.P2597_C02(SCH_1):PAGE14; MAT: Ferrite; MAX_CURRENT: 0.5A; NV_PN: 100-0183-000; PACK_TYPE: BEAD_0402; PATH: I240; PHYS_PAGE: 14; Q: [ ]; ROT: 0; SEC: 1; SELF_RESONANCE_FREQ: N/A; SIGNAL_MODEL: nv_ind_noxnet; TOL: 25%; VER: 1; XY: (-8500,1500)
LB4 = L: ACOUSTIC_MARGIN: N/A; ASSEMBLY: HDMI; CDS_LIB: discrete; CDS_PART_NAME: L_BEAD_0402-600OHM,FERRITE,25%,0.5A,0.5A,0.39OHM,[ ],N/A,N/A,100-0183-000; CDS_PHYS_PART_NAME: L_BEAD_0402-600OHM,FERRITE,25%,0.5A,0.5A,0.39OHM,[ ],N/A,N/A,100-0183-000-100-0183-000,600OHM; CDS_SEC: 1; CONTINUOUS_CURRENT: 0.5A; DC_RESISTANCE: 0.39ohm; DEVICE_TYPENAME: L_BEAD_0402-600OHMFERRITE2505A05A039OHMNANA100-0183-000-100-0183-000600OHM; DRAWING: @P2597_C02_LIB.P2597_C02(SCH_1):PAGE14; MAT: Ferrite; MAX_CURRENT: 0.5A; NV_PN: 100-0183-000; PACK_TYPE: BEAD_0402; PATH: I241; PHYS_PAGE: 14; Q: [ ]; ROT: 0; SEC: 1; SELF_RESONANCE_FREQ: N/A; SIGNAL_MODEL: nv_ind_noxnet; TOL: 25%; VER: 1; XY: (-8500,1600)
LB5 = L: ACOUSTIC_MARGIN: N/A; ASSEMBLY: HDMI; CDS_LIB: discrete; CDS_PART_NAME: L_BEAD_0402-600OHM,FERRITE,25%,0.5A,0.5A,0.39OHM,[ ],N/A,N/A,100-0183-000; CDS_PHYS_PART_NAME: L_BEAD_0402-600OHM,FERRITE,25%,0.5A,0.5A,0.39OHM,[ ],N/A,N/A,100-0183-000-100-0183-000,600OHM; CDS_SEC: 1; CONTINUOUS_CURRENT: 0.5A; DC_RESISTANCE: 0.39ohm; DEVICE_TYPENAME: L_BEAD_0402-600OHMFERRITE2505A05A039OHMNANA100-0183-000-100-0183-000600OHM; DRAWING: @P2597_C02_LIB.P2597_C02(SCH_1):PAGE14; MAT: Ferrite; MAX_CURRENT: 0.5A; NV_PN: 100-0183-000; PACK_TYPE: BEAD_0402; PATH: I242; PHYS_PAGE: 14; Q: [ ]; ROT: 0; SEC: 1; SELF_RESONANCE_FREQ: N/A; SIGNAL_MODEL: nv_ind_noxnet; TOL: 25%; VER: 1; XY: (-8500,1700)
LB6 = L: ACOUSTIC_MARGIN: N/A; ASSEMBLY: HDMI; CDS_LIB: discrete; CDS_PART_NAME: L_BEAD_0402-600OHM,FERRITE,25%,0.5A,0.5A,0.39OHM,[ ],N/A,N/A,100-0183-000; CDS_PHYS_PART_NAME: L_BEAD_0402-600OHM,FERRITE,25%,0.5A,0.5A,0.39OHM,[ ],N/A,N/A,100-0183-000-100-0183-000,600OHM; CDS_SEC: 1; CONTINUOUS_CURRENT: 0.5A; DC_RESISTANCE: 0.39ohm; DEVICE_TYPENAME: L_BEAD_0402-600OHMFERRITE2505A05A039OHMNANA100-0183-000-100-0183-000600OHM; DRAWING: @P2597_C02_LIB.P2597_C02(SCH_1):PAGE14; MAT: Ferrite; MAX_CURRENT: 0.5A; NV_PN: 100-0183-000; PACK_TYPE: BEAD_0402; PATH: I243; PHYS_PAGE: 14; Q: [ ]; ROT: 0; SEC: 1; SELF_RESONANCE_FREQ: N/A; SIGNAL_MODEL: nv_ind_noxnet; TOL: 25%; VER: 1; XY: (-8500,1800)
LB7 = L: ACOUSTIC_MARGIN: N/A; ASSEMBLY: HDMI; CDS_LIB: discrete; CDS_PART_NAME: L_BEAD_0402-600OHM,FERRITE,25%,0.5A,0.5A,0.39OHM,[ ],N/A,N/A,100-0183-000; CDS_PHYS_PART_NAME: L_BEAD_0402-600OHM,FERRITE,25%,0.5A,0.5A,0.39OHM,[ ],N/A,N/A,100-0183-000-100-0183-000,600OHM; CDS_SEC: 1; CONTINUOUS_CURRENT: 0.5A; DC_RESISTANCE: 0.39ohm; DEVICE_TYPENAME: L_BEAD_0402-600OHMFERRITE2505A05A039OHMNANA100-0183-000-100-0183-000600OHM; DRAWING: @P2597_C02_LIB.P2597_C02(SCH_1):PAGE14; MAT: Ferrite; MAX_CURRENT: 0.5A; NV_PN: 100-0183-000; PACK_TYPE: BEAD_0402; PATH: I244; PHYS_PAGE: 14; Q: [ ]; ROT: 0; SEC: 1; SELF_RESONANCE_FREQ: N/A; SIGNAL_MODEL: nv_ind_noxnet; TOL: 25%; VER: 1; XY: (-8500,1900)
LB8 = L: ACOUSTIC_MARGIN: N/A; ASSEMBLY: HDMI; CDS_LIB: discrete; CDS_PART_NAME: L_BEAD_0402-600OHM,FERRITE,25%,0.5A,0.5A,0.39OHM,[ ],N/A,N/A,100-0183-000; CDS_PHYS_PART_NAME: L_BEAD_0402-600OHM,FERRITE,25%,0.5A,0.5A,0.39OHM,[ ],N/A,N/A,100-0183-000-100-0183-000,600OHM; CDS_SEC: 1; CONTINUOUS_CURRENT: 0.5A; DC_RESISTANCE: 0.39ohm; DEVICE_TYPENAME: L_BEAD_0402-600OHMFERRITE2505A05A039OHMNANA100-0183-000-100-0183-000600OHM; DRAWING: @P2597_C02_LIB.P2597_C02(SCH_1):PAGE14; MAT: Ferrite; MAX_CURRENT: 0.5A; NV_PN: 100-0183-000; PACK_TYPE: BEAD_0402; PATH: I245; PHYS_PAGE: 14; Q: [ ]; ROT: 0; SEC: 1; SELF_RESONANCE_FREQ: N/A; SIGNAL_MODEL: nv_ind_noxnet; TOL: 25%; VER: 1; XY: (-8500,2000)
LB9 = L: ACOUSTIC_MARGIN: N/A; ASSEMBLY: HDMI; CDS_LIB: discrete; CDS_PART_NAME: L_BEAD_0402-30OHM,FERRITE,25%,[ ],2A,0.1OHM,[ ],N/A,N/A,100-0165-000; CDS_PHYS_PART_NAME: L_BEAD_0402-30OHM,FERRITE,25%,[ ],2A,0.1OHM,[ ],N/A,N/A,100-0165-000-100-0165-000,30OHM; CDS_SEC: 1; CONTINUOUS_CURRENT: [ ]; DC_RESISTANCE: 0.1ohm; DEVICE_TYPENAME: L_BEAD_0402-30OHMFERRITE252A01OHMNANA100-0165-000-100-0165-00030OHM; DRAWING: @P2597_C02_LIB.P2597_C02(SCH_1):PAGE14; MAT: Ferrite; MAX_CURRENT: 2A; NV_PN: 100-0165-000; PACK_TYPE: BEAD_0402; PATH: I264; PHYS_PAGE: 14; Q: [ ]; ROT: 0; SEC: 1; SELF_RESONANCE_FREQ: N/A; SIGNAL_MODEL: nv_ind_noxnet; TOL: 25%; VER: 1; XY: (-11300,6950)
Q505 = Q_FET_N_ENH#2: ASSEMBLY: HDMI; CDS_LIB: discrete; CDS_PART_NAME: Q_FET_N_ENH_DFN1006-DMN26D0UFB4,20V,999MOHM@10V / 3000MOHM@4.5V / 4000MOHM@2.5V,0.14A,0.805A,10V,0.35W,999NC@10V / 999NC@4.5V A; CDS_PHYS_PART_NAME: Q_FET_N_ENH_DFN1006-DMN26D0UFB4,20V,999MOHM@10V / 3000MOHM@4.5V / 4000MOHM@2.5V,0.14A,0.805A,10V,0.35W,999NC@10V / 999NC@4.5V B; CDS_SEC: 1; CONTINUOUS_CURRENT: 0.14A; CaptureCellPackProp: Q_FET_N_ENH__sym_2##2; DEVICE_TYPENAME: Q_FET_N_ENH_DFN1006-DMN26D0UFB420V999MOHM10V3000MOHM45V4000MOHM25V014A0805A10V035W999NC10V999NC45VB; DRAWING: @P2597_C02_LIB.P2597_C02(SCH_1):PAGE14; MAX_CURRENT: 0.805A; MAX_VOLTAGE: 20V; MAX_WATTAGE: 0.35W; NV_NAME: DMN26D0UFB4; NV_PN: 300-0868-000; PACK_TYPE: DFN1006; PATH: I362; PHYS_PAGE: 14; Q_G: 999nC@10V / 999nC@4.5V / 999nC@2.5V; ROT: 0; R_DS_ON: 999mohm@10V / 3000mohm@4.5V / 4000mohm@2.5V; SEC: 1; VER: 2; V_BE_GS: 10V; XY: (-9500,1200)
Q506 = Q_FET_N_ENH#1: ASSEMBLY: HDMI; CDS_LIB: discrete; CDS_PART_NAME: Q_FET_N_ENH_SOT363-NTJD4001N,30V,1500MOHM@10V / 1500MOHM@4.5V / 1500MOHM@2.5V,0.25A,0.25A,20V,0.272W,[ ]@10V / [ ]@4.5V / [ ]@A; CDS_PHYS_PART_NAME: Q_FET_N_ENH_SOT363-NTJD4001N,30V,1500MOHM@10V / 1500MOHM@4.5V / 1500MOHM@2.5V,0.25A,0.25A,20V,0.272W,[ ]@10V / [ ]@4.5V / [ ]@B; CDS_SEC: 1; CONTINUOUS_CURRENT: 0.25A; CaptureCellPackProp: Q_FET_N_ENH__sym_2##1; DEVICE_TYPENAME: Q_FET_N_ENH_SOT363-NTJD4001N30V1500MOHM10V1500MOHM45V1500MOHM25V025A025A20V0272W10V45VB; DRAWING: @P2597_C02_LIB.P2597_C02(SCH_1):PAGE14; MAX_CURRENT: 0.25A; MAX_VOLTAGE: 30V; MAX_WATTAGE: 0.272W; NV_NAME: NTJD4001N; NV_PN: 300-0402-000; PACK_TYPE: SOT363; PATH: I312; PHYS_PAGE: 14; Q_G: [ ]@10V / [ ]@4.5V / [ ]@2.5V; ROT: 5; R_DS_ON: 1500mohm@10V / 1500mohm@4.5V / 1500mohm@2.5V; SEC: 1; SEC_TYPE: SOT363; VER: 2; V_BE_GS: 20V; XY: (-5800,6000)
Q507 = Q_NPN: ASSEMBLY: HDMI; CDS_LIB: discrete; CDS_PART_NAME: Q_NPN_DFN1006-MMBT3904LP-7,40V,0.3V,0.2A,9999A,6V,0.25W,300-0869-000; CDS_PHYS_PART_NAME: Q_NPN_DFN1006-MMBT3904LP-7,40V,0.3V,0.2A,9999A,6V,0.25W,300-0869-000-300-0869-000; CDS_SEC: 1; CONTINUOUS_CURRENT: 0.2A; DEVICE_TYPENAME: Q_NPN_DFN1006-MMBT3904LP-740V03V02A9999A6V025W300-0869-000-300-0869-000; DRAWING: @P2597_C02_LIB.P2597_C02(SCH_1):PAGE14; MAX_CURRENT: 9999A; MAX_VOLTAGE: 40V; MAX_WATTAGE: 0.25W; NV_NAME: MMBT3904LP-7; NV_PN: 300-0869-000; PACK_TYPE: DFN1006; PATH: I352; PHYS_PAGE: 14; ROT: 2; SEC: 1; VER: 1; V_BE_GS: 6V; V_CE_SAT: 0.3V; XY: (-3800,6700)
Q508 = Q_FET_N_ENH#2: ASSEMBLY: HDMI; CDS_LIB: discrete; CDS_PART_NAME: Q_FET_N_ENH_SOT23_1G1D1S-FDV301N,25V,-1000MOHM@10V / 4000MOHM@4.5V / -1000MOHM@2.5V,0.22A,0.5A,8V,0.35W,[ ]@10V / [ ]@4.5V / [A; CDS_PHYS_PART_NAME: Q_FET_N_ENH_SOT23_1G1D1S-FDV301N,25V,-1000MOHM@10V / 4000MOHM@4.5V / -1000MOHM@2.5V,0.22A,0.5A,8V,0.35W,[ ]@10V / [ ]@4.5V / [B; CDS_SEC: 1; CONTINUOUS_CURRENT: 0.22A; CaptureCellPackProp: Q_FET_N_ENH__sym_2##2; DEVICE_TYPENAME: Q_FET_N_ENH_SOT23_1G1D1S-FDV301N25V-1000MOHM10V4000MOHM45V-1000MOHM25V022A05A8V035W10V45VB; DRAWING: @P2597_C02_LIB.P2597_C02(SCH_1):PAGE14; MAX_CURRENT: 0.5A; MAX_VOLTAGE: 25V; MAX_WATTAGE: 0.35W; NV_NAME: FDV301N; NV_PN: 300-0494-000; PACK_TYPE: SOT23_1G1D1S; PATH: I317; PHYS_PAGE: 14; Q_G: [ ]@10V / [ ]@4.5V / [ ]@2.5V; ROT: 5; R_DS_ON: -1000mohm@10V / 4000mohm@4.5V / -1000mohm@2.5V; SEC: 1; VER: 2; V_BE_GS: 8V; XY: (-5050,4900)
R544 = R#1: ASSEMBLY: HDMI; CDS_LIB: discrete; CDS_PART_NAME: R_0402-100K,1 %,62.5MW,195-0005-000; CDS_PHYS_PART_NAME: R_0402-100K,1 %,62.5MW,195-0005-000-100K,195-0005-000; CDS_SEC: 1; CHIPS_PART_NAME: R; DEVICE_TYPENAME: R_0402-100K1625MW195-0005-000-100K195-0005-000; DRAWING: @P2597_C02_LIB.P2597_C02(SCH_1):PAGE14; MAX_WATTAGE: 62.5mW; NV_PN: 195-0005-000; PATH: I370; PHYS_PAGE: 14; ROT: 0; SEC: 1; SIGNAL_MODEL: nv_res; TOL: 1%; VER: 2; XY: (-11200,5900)
R547 = R: ASSEMBLY: HDMI; CDS_LIB: discrete; CDS_PART_NAME: R_0402-0OHM,0.05 OHM,62.5MW,195-2655-000; CDS_PHYS_PART_NAME: R_0402-0OHM,0.05 OHM,62.5MW,195-2655-000-0OHM,195-2655-000; CDS_SEC: 1; DEVICE_TYPENAME: R_0402-0OHM005OHM625MW195-2655-000-0OHM195-2655-000; DRAWING: @P2597_C02_LIB.P2597_C02(SCH_1):PAGE14; MAX_WATTAGE: 62.5mW; NV_PN: 195-2655-000; PATH: I270; PHYS_PAGE: 14; ROT: 0; SEC: 1; SIGNAL_MODEL: nv_res; TOL: 0.05 ohm; VER: 1; XY: (-10000,6250)
R548 = R: ASSEMBLY: HDMI; CDS_LIB: discrete; CDS_PART_NAME: R_0402-4.7K,5 %,62.5MW,195-0598-000; CDS_PHYS_PART_NAME: R_0402-4.7K,5 %,62.5MW,195-0598-000-195-0598-000,4.7K; CDS_SEC: 1; DEVICE_TYPENAME: R_0402-47K5625MW195-0598-000-195-0598-00047K; DRAWING: @P2597_C02_LIB.P2597_C02(SCH_1):PAGE14; MAX_WATTAGE: 62.5mW; NV_PN: 195-0598-000; PATH: I267; PHYS_PAGE: 14; ROT: 0; SEC: 1; SIGNAL_MODEL: nv_res; TOL: 5%; VER: 1; XY: (-10750,6100)
R549 = R: ASSEMBLY: HDMI; CDS_LIB: discrete; CDS_PART_NAME: R_0402-4.7K,5 %,62.5MW,195-0598-000; CDS_PHYS_PART_NAME: R_0402-4.7K,5 %,62.5MW,195-0598-000-195-0598-000,4.7K; CDS_SEC: 1; DEVICE_TYPENAME: R_0402-47K5625MW195-0598-000-195-0598-00047K; DRAWING: @P2597_C02_LIB.P2597_C02(SCH_1):PAGE14; MAX_WATTAGE: 62.5mW; NV_PN: 195-0598-000; PATH: I268; PHYS_PAGE: 14; ROT: 0; SEC: 1; SIGNAL_MODEL: nv_res; SKU: NO STUFF; TOL: 5%; VER: 1; XY: (-11150,6250)
R550 = R#1: ASSEMBLY: HDMI; CDS_LIB: discrete; CDS_PART_NAME: R_0402-88.7K,1 %,62.5MW,195-0460-000; CDS_PHYS_PART_NAME: R_0402-88.7K,1 %,62.5MW,195-0460-000-195-0460-000,88.7K; CDS_SEC: 1; CHIPS_PART_NAME: R; DEVICE_TYPENAME: R_0402-887K1625MW195-0460-000-195-0460-000887K; DRAWING: @P2597_C02_LIB.P2597_C02(SCH_1):PAGE14; MAX_WATTAGE: 62.5mW; NV_PN: 195-0460-000; PATH: I274; PHYS_PAGE: 14; ROT: 0; SEC: 1; SIGNAL_MODEL: nv_res; TOL: 1%; VER: 2; XY: (-8150,6100)
R557 = R: ASSEMBLY: HDMI; CDS_LIB: discrete; CDS_PART_NAME: R_0402-0OHM,0.05 OHM,62.5MW,195-2655-000; CDS_PHYS_PART_NAME: R_0402-0OHM,0.05 OHM,62.5MW,195-2655-000-0OHM,195-2655-000; CDS_SEC: 1; DEVICE_TYPENAME: R_0402-0OHM005OHM625MW195-2655-000-0OHM195-2655-000; DRAWING: @P2597_C02_LIB.P2597_C02(SCH_1):PAGE14; MAX_WATTAGE: 62.5mW; NV_PN: 195-2655-000; PATH: I360; PHYS_PAGE: 14; ROT: 0; SEC: 1; SIGNAL_MODEL: nv_res; TOL: 0.05 ohm; VER: 1; XY: (-10450,950)
R558 = R: ASSEMBLY: HDMI; CDS_LIB: discrete; CDS_PART_NAME: R_0402-0OHM,0.05 OHM,62.5MW,195-2655-000; CDS_PHYS_PART_NAME: R_0402-0OHM,0.05 OHM,62.5MW,195-2655-000-0OHM,195-2655-000; CDS_SEC: 1; DEVICE_TYPENAME: R_0402-0OHM005OHM625MW195-2655-000-0OHM195-2655-000; DRAWING: @P2597_C02_LIB.P2597_C02(SCH_1):PAGE14; MAX_WATTAGE: 62.5mW; NV_PN: 195-2655-000; PATH: I361; PHYS_PAGE: 14; ROT: 0; SEC: 1; SIGNAL_MODEL: nv_res; SKU: NO STUFF; TOL: 0.05 ohm; VER: 1; XY: (-10450,1150)
R559 = R#1: ASSEMBLY: HDMI; CDS_LIB: discrete; CDS_PART_NAME: R_0402-10K,5 %,62.5MW,195-0486-000; CDS_PHYS_PART_NAME: R_0402-10K,5 %,62.5MW,195-0486-000-10K,195-0486-000; CDS_SEC: 1; CHIPS_PART_NAME: R; DEVICE_TYPENAME: R_0402-10K5625MW195-0486-000-10K195-0486-000; DRAWING: @P2597_C02_LIB.P2597_C02(SCH_1):PAGE14; MAX_WATTAGE: 62.5mW; NV_PN: 195-0486-000; PATH: I308; PHYS_PAGE: 14; ROT: 2; SEC: 1; SIGNAL_MODEL: nv_res; TOL: 5%; VER: 2; XY: (-6650,6250)
R560 = R#1: ASSEMBLY: HDMI; CDS_LIB: discrete; CDS_PART_NAME: R_0402-0OHM,0.05 OHM,62.5MW,195-2655-000; CDS_PHYS_PART_NAME: R_0402-0OHM,0.05 OHM,62.5MW,195-2655-000-0OHM,195-2655-000; CDS_SEC: 1; CHIPS_PART_NAME: R; DEVICE_TYPENAME: R_0402-0OHM005OHM625MW195-2655-000-0OHM195-2655-000; DRAWING: @P2597_C02_LIB.P2597_C02(SCH_1):PAGE14; MAX_WATTAGE: 62.5mW; NV_PN: 195-2655-000; PATH: I309; PHYS_PAGE: 14; ROT: 2; SEC: 1; SIGNAL_MODEL: nv_res; TOL: 0.05 ohm; VER: 2; XY: (-6300,6250)
R561 = R#1: ASSEMBLY: HDMI; CDS_LIB: discrete; CDS_PART_NAME: R_0402-1.8K,5 %,62.5MW,195-0528-000; CDS_PHYS_PART_NAME: R_0402-1.8K,5 %,62.5MW,195-0528-000-1.8K,195-0528-000; CDS_SEC: 1; CHIPS_PART_NAME: R; DEVICE_TYPENAME: R_0402-18K5625MW195-0528-000-18K195-0528-000; DRAWING: @P2597_C02_LIB.P2597_C02(SCH_1):PAGE14; MAX_WATTAGE: 62.5mW; NV_PN: 195-0528-000; PATH: I321; PHYS_PAGE: 14; ROT: 0; SEC: 1; SIGNAL_MODEL: nv_res; TOL: 5%; VER: 2; XY: (-4950,5800)
R562 = R: ASSEMBLY: HDMI; CDS_LIB: discrete; CDS_PART_NAME: R_0402-499OHM,1 %,62.5MW,195-0338-000; CDS_PHYS_PART_NAME: R_0402-499OHM,1 %,62.5MW,195-0338-000-195-0338-000,499OHM; CDS_SEC: 1; DEVICE_TYPENAME: R_0402-499OHM1625MW195-0338-000-195-0338-000499OHM; DRAWING: @P2597_C02_LIB.P2597_C02(SCH_1):PAGE14; MAX_WATTAGE: 62.5mW; NO_XNET_CONNECTION: 1; NV_PN: 195-0338-000; PATH: I283; PHYS_PAGE: 14; ROT: 0; SEC: 1; SIGNAL_MODEL: nv_res; TOL: 1%; VER: 1; XY: (-7800,2000)
R563 = R: ASSEMBLY: HDMI; CDS_LIB: discrete; CDS_PART_NAME: R_0402-3.3OHM,5 %,62.5MW,195-0567-000; CDS_PHYS_PART_NAME: R_0402-3.3OHM,5 %,62.5MW,195-0567-000-195-0567-000,3.3OHM; CDS_SEC: 1; DEVICE_TYPENAME: R_0402-33OHM5625MW195-0567-000-195-0567-00033OHM; DRAWING: @P2597_C02_LIB.P2597_C02(SCH_1):PAGE14; MAX_WATTAGE: 62.5mW; NV_PN: 195-0567-000; PATH: I302; PHYS_PAGE: 14; PLACEMENT_NOTE: CoLayout with L501; ROT: 0; SEC: 1; SIGNAL_MODEL: nv_res; TOL: 5%; VER: 1; XY: (-4500,4250)
R564 = R: ASSEMBLY: HDMI; CDS_LIB: discrete; CDS_PART_NAME: R_0402-0OHM,0.05 OHM,62.5MW,195-2655-000; CDS_PHYS_PART_NAME: R_0402-0OHM,0.05 OHM,62.5MW,195-2655-000-0OHM,195-2655-000; CDS_SEC: 1; DEVICE_TYPENAME: R_0402-0OHM005OHM625MW195-2655-000-0OHM195-2655-000; DRAWING: @P2597_C02_LIB.P2597_C02(SCH_1):PAGE14; MAX_WATTAGE: 62.5mW; NV_PN: 195-2655-000; PATH: I324; PHYS_PAGE: 14; ROT: 0; SEC: 1; SIGNAL_MODEL: nv_res; TOL: 0.05 ohm; VER: 1; XY: (-4350,5600)
R565 = R: ASSEMBLY: HDMI; CDS_LIB: discrete; CDS_PART_NAME: R_0402-3.3OHM,5 %,62.5MW,195-0567-000; CDS_PHYS_PART_NAME: R_0402-3.3OHM,5 %,62.5MW,195-0567-000-195-0567-000,3.3OHM; CDS_SEC: 1; DEVICE_TYPENAME: R_0402-33OHM5625MW195-0567-000-195-0567-00033OHM; DRAWING: @P2597_C02_LIB.P2597_C02(SCH_1):PAGE14; MAX_WATTAGE: 62.5mW; NV_PN: 195-0567-000; PATH: I300; PHYS_PAGE: 14; PLACEMENT_NOTE: CoLayout with L501; ROT: 0; SEC: 1; SIGNAL_MODEL: nv_res; TOL: 5%; VER: 1; XY: (-4500,3900)
R566 = R: ASSEMBLY: HDMI; CDS_LIB: discrete; CDS_PART_NAME: R_0402-499OHM,1 %,62.5MW,195-0338-000; CDS_PHYS_PART_NAME: R_0402-499OHM,1 %,62.5MW,195-0338-000-195-0338-000,499OHM; CDS_SEC: 1; DEVICE_TYPENAME: R_0402-499OHM1625MW195-0338-000-195-0338-000499OHM; DRAWING: @P2597_C02_LIB.P2597_C02(SCH_1):PAGE14; MAX_WATTAGE: 62.5mW; NO_XNET_CONNECTION: 1; NV_PN: 195-0338-000; PATH: I282; PHYS_PAGE: 14; ROT: 0; SEC: 1; SIGNAL_MODEL: nv_res; TOL: 1%; VER: 1; XY: (-7800,1900)
R567 = R: ASSEMBLY: HDMI; CDS_LIB: discrete; CDS_PART_NAME: R_0402-499OHM,1 %,62.5MW,195-0338-000; CDS_PHYS_PART_NAME: R_0402-499OHM,1 %,62.5MW,195-0338-000-195-0338-000,499OHM; CDS_SEC: 1; DEVICE_TYPENAME: R_0402-499OHM1625MW195-0338-000-195-0338-000499OHM; DRAWING: @P2597_C02_LIB.P2597_C02(SCH_1):PAGE14; MAX_WATTAGE: 62.5mW; NO_XNET_CONNECTION: 1; NV_PN: 195-0338-000; PATH: I281; PHYS_PAGE: 14; ROT: 0; SEC: 1; SIGNAL_MODEL: nv_res; TOL: 1%; VER: 1; XY: (-7800,1800)
R568 = R: ASSEMBLY: HDMI; CDS_LIB: discrete; CDS_PART_NAME: R_0402-5.6OHM,5 %,62.5MW,195-0609-000; CDS_PHYS_PART_NAME: R_0402-5.6OHM,5 %,62.5MW,195-0609-000-195-0609-000,5.6OHM; CDS_SEC: 1; DEVICE_TYPENAME: R_0402-56OHM5625MW195-0609-000-195-0609-00056OHM; DRAWING: @P2597_C02_LIB.P2597_C02(SCH_1):PAGE14; MAX_WATTAGE: 62.5mW; NV_PN: 195-0609-000; PATH: I299; PHYS_PAGE: 14; PLACEMENT_NOTE: CoLayout with L503; ROT: 0; SEC: 1; SIGNAL_MODEL: nv_res; TOL: 5%; VER: 1; XY: (-4500,3750)
R569 = R: ASSEMBLY: HDMI; CDS_LIB: discrete; CDS_PART_NAME: R_0402-0OHM,0.05 OHM,62.5MW,195-2655-000; CDS_PHYS_PART_NAME: R_0402-0OHM,0.05 OHM,62.5MW,195-2655-000-0OHM,195-2655-000; CDS_SEC: 1; DEVICE_TYPENAME: R_0402-0OHM005OHM625MW195-2655-000-0OHM195-2655-000; DRAWING: @P2597_C02_LIB.P2597_C02(SCH_1):PAGE14; MAX_WATTAGE: 62.5mW; NV_PN: 195-2655-000; PATH: I320; PHYS_PAGE: 14; ROT: 0; SEC: 1; SIGNAL_MODEL: nv_res; TOL: 0.05 ohm; VER: 1; XY: (-4350,5500)
R570 = R#1: ASSEMBLY: HDMI; CDS_LIB: discrete; CDS_PART_NAME: R_0402-10K,5 %,62.5MW,195-0486-000; CDS_PHYS_PART_NAME: R_0402-10K,5 %,62.5MW,195-0486-000-10K,195-0486-000; CDS_SEC: 1; CHIPS_PART_NAME: R; DEVICE_TYPENAME: R_0402-10K5625MW195-0486-000-10K195-0486-000; DRAWING: @P2597_C02_LIB.P2597_C02(SCH_1):PAGE14; MAX_WATTAGE: 62.5mW; NV_PN: 195-0486-000; PATH: I351; PHYS_PAGE: 14; ROT: 2; SEC: 1; SIGNAL_MODEL: nv_res; TOL: 5%; VER: 2; XY: (-4050,7000)
R571 = R: ASSEMBLY: HDMI; CDS_LIB: discrete; CDS_PART_NAME: R_0402-5.6OHM,5 %,62.5MW,195-0609-000; CDS_PHYS_PART_NAME: R_0402-5.6OHM,5 %,62.5MW,195-0609-000-195-0609-000,5.6OHM; CDS_SEC: 1; DEVICE_TYPENAME: R_0402-56OHM5625MW195-0609-000-195-0609-00056OHM; DRAWING: @P2597_C02_LIB.P2597_C02(SCH_1):PAGE14; MAX_WATTAGE: 62.5mW; NV_PN: 195-0609-000; PATH: I297; PHYS_PAGE: 14; PLACEMENT_NOTE: CoLayout with L503; ROT: 0; SEC: 1; SIGNAL_MODEL: nv_res; TOL: 5%; VER: 1; XY: (-4500,3400)
R572 = R#1: ASSEMBLY: HDMI; CDS_LIB: discrete; CDS_PART_NAME: R_0402-0OHM,0.05 OHM,62.5MW,195-2655-000; CDS_PHYS_PART_NAME: R_0402-0OHM,0.05 OHM,62.5MW,195-2655-000-0OHM,195-2655-000; CDS_SEC: 1; CHIPS_PART_NAME: R; DEVICE_TYPENAME: R_0402-0OHM005OHM625MW195-2655-000-0OHM195-2655-000; DRAWING: @P2597_C02_LIB.P2597_C02(SCH_1):PAGE14; MAX_WATTAGE: 62.5mW; NV_PN: 195-2655-000; PATH: I313; PHYS_PAGE: 14; ROT: 2; SEC: 1; SIGNAL_MODEL: nv_res; TOL: 0.05 ohm; VER: 2; XY: (-5850,6250)
R573 = R#1: ASSEMBLY: HDMI; CDS_LIB: discrete; CDS_PART_NAME: R_0402-10K,5 %,62.5MW,195-0486-000; CDS_PHYS_PART_NAME: R_0402-10K,5 %,62.5MW,195-0486-000-10K,195-0486-000; CDS_SEC: 1; CHIPS_PART_NAME: R; DEVICE_TYPENAME: R_0402-10K5625MW195-0486-000-10K195-0486-000; DRAWING: @P2597_C02_LIB.P2597_C02(SCH_1):PAGE14; MAX_WATTAGE: 62.5mW; NV_PN: 195-0486-000; PATH: I306; PHYS_PAGE: 14; ROT: 2; SEC: 1; SIGNAL_MODEL: nv_res; TOL: 5%; VER: 2; XY: (-7100,6250)
R574 = R#1: ASSEMBLY: HDMI; CDS_LIB: discrete; CDS_PART_NAME: R_0402-1.8K,5 %,62.5MW,195-0528-000; CDS_PHYS_PART_NAME: R_0402-1.8K,5 %,62.5MW,195-0528-000-1.8K,195-0528-000; CDS_SEC: 1; CHIPS_PART_NAME: R; DEVICE_TYPENAME: R_0402-18K5625MW195-0528-000-18K195-0528-000; DRAWING: @P2597_C02_LIB.P2597_C02(SCH_1):PAGE14; MAX_WATTAGE: 62.5mW; NV_PN: 195-0528-000; PATH: I323; PHYS_PAGE: 14; ROT: 0; SEC: 1; SIGNAL_MODEL: nv_res; TOL: 5%; VER: 2; XY: (-4700,5800)
R575 = R: ASSEMBLY: HDMI; CDS_LIB: discrete; CDS_PART_NAME: R_0402-499OHM,1 %,62.5MW,195-0338-000; CDS_PHYS_PART_NAME: R_0402-499OHM,1 %,62.5MW,195-0338-000-195-0338-000,499OHM; CDS_SEC: 1; DEVICE_TYPENAME: R_0402-499OHM1625MW195-0338-000-195-0338-000499OHM; DRAWING: @P2597_C02_LIB.P2597_C02(SCH_1):PAGE14; MAX_WATTAGE: 62.5mW; NO_XNET_CONNECTION: 1; NV_PN: 195-0338-000; PATH: I280; PHYS_PAGE: 14; ROT: 0; SEC: 1; SIGNAL_MODEL: nv_res; TOL: 1%; VER: 1; XY: (-7800,1700)
R576 = R: ASSEMBLY: HDMI; CDS_LIB: discrete; CDS_PART_NAME: R_0402-499OHM,1 %,62.5MW,195-0338-000; CDS_PHYS_PART_NAME: R_0402-499OHM,1 %,62.5MW,195-0338-000-195-0338-000,499OHM; CDS_SEC: 1; DEVICE_TYPENAME: R_0402-499OHM1625MW195-0338-000-195-0338-000499OHM; DRAWING: @P2597_C02_LIB.P2597_C02(SCH_1):PAGE14; MAX_WATTAGE: 62.5mW; NO_XNET_CONNECTION: 1; NV_PN: 195-0338-000; PATH: I279; PHYS_PAGE: 14; ROT: 0; SEC: 1; SIGNAL_MODEL: nv_res; TOL: 1%; VER: 1; XY: (-7800,1600)
R577 = R: ASSEMBLY: HDMI; CDS_LIB: discrete; CDS_PART_NAME: R_0402-5.6OHM,5 %,62.5MW,195-0609-000; CDS_PHYS_PART_NAME: R_0402-5.6OHM,5 %,62.5MW,195-0609-000-195-0609-000,5.6OHM; CDS_SEC: 1; DEVICE_TYPENAME: R_0402-56OHM5625MW195-0609-000-195-0609-00056OHM; DRAWING: @P2597_C02_LIB.P2597_C02(SCH_1):PAGE14; MAX_WATTAGE: 62.5mW; NV_PN: 195-0609-000; PATH: I296; PHYS_PAGE: 14; PLACEMENT_NOTE: CoLayout with L504; ROT: 0; SEC: 1; SIGNAL_MODEL: nv_res; TOL: 5%; VER: 1; XY: (-4500,3250)
R578 = R#1: ASSEMBLY: HDMI; CDS_LIB: discrete; CDS_PART_NAME: R_0402-100K,1 %,62.5MW,195-0005-000; CDS_PHYS_PART_NAME: R_0402-100K,1 %,62.5MW,195-0005-000-100K,195-0005-000; CDS_SEC: 1; CHIPS_PART_NAME: R; DEVICE_TYPENAME: R_0402-100K1625MW195-0005-000-100K195-0005-000; DRAWING: @P2597_C02_LIB.P2597_C02(SCH_1):PAGE14; MAX_WATTAGE: 62.5mW; NV_PN: 195-0005-000; PATH: I347; PHYS_PAGE: 14; ROT: 2; SEC: 1; SIGNAL_MODEL: nv_res; TOL: 1%; VER: 2; XY: (-3550,6500)
R579 = R: ASSEMBLY: HDMI; CDS_LIB: discrete; CDS_PART_NAME: R_0402-5.6OHM,5 %,62.5MW,195-0609-000; CDS_PHYS_PART_NAME: R_0402-5.6OHM,5 %,62.5MW,195-0609-000-195-0609-000,5.6OHM; CDS_SEC: 1; DEVICE_TYPENAME: R_0402-56OHM5625MW195-0609-000-195-0609-00056OHM; DRAWING: @P2597_C02_LIB.P2597_C02(SCH_1):PAGE14; MAX_WATTAGE: 62.5mW; NV_PN: 195-0609-000; PATH: I294; PHYS_PAGE: 14; PLACEMENT_NOTE: CoLayout with L504; ROT: 0; SEC: 1; SIGNAL_MODEL: nv_res; TOL: 5%; VER: 1; XY: (-4500,2900)
R580 = R: ASSEMBLY: HDMI; CDS_LIB: discrete; CDS_PART_NAME: R_0402-100K,1 %,62.5MW,195-0005-000; CDS_PHYS_PART_NAME: R_0402-100K,1 %,62.5MW,195-0005-000-100K,195-0005-000; CDS_SEC: 1; DEVICE_TYPENAME: R_0402-100K1625MW195-0005-000-100K195-0005-000; DRAWING: @P2597_C02_LIB.P2597_C02(SCH_1):PAGE14; MAX_WATTAGE: 62.5mW; NV_PN: 195-0005-000; PATH: I354; PHYS_PAGE: 14; ROT: 2; SEC: 1; SIGNAL_MODEL: nv_res; TOL: 1%; VER: 1; XY: (-3250,6700)
R581 = R: ASSEMBLY: HDMI; CDS_LIB: discrete; CDS_PART_NAME: R_0402-499OHM,1 %,62.5MW,195-0338-000; CDS_PHYS_PART_NAME: R_0402-499OHM,1 %,62.5MW,195-0338-000-195-0338-000,499OHM; CDS_SEC: 1; DEVICE_TYPENAME: R_0402-499OHM1625MW195-0338-000-195-0338-000499OHM; DRAWING: @P2597_C02_LIB.P2597_C02(SCH_1):PAGE14; MAX_WATTAGE: 62.5mW; NO_XNET_CONNECTION: 1; NV_PN: 195-0338-000; PATH: I278; PHYS_PAGE: 14; ROT: 0; SEC: 1; SIGNAL_MODEL: nv_res; TOL: 1%; VER: 1; XY: (-7800,1500)
R582 = R: ASSEMBLY: HDMI; CDS_LIB: discrete; CDS_PART_NAME: R_0402-499OHM,1 %,62.5MW,195-0338-000; CDS_PHYS_PART_NAME: R_0402-499OHM,1 %,62.5MW,195-0338-000-195-0338-000,499OHM; CDS_SEC: 1; DEVICE_TYPENAME: R_0402-499OHM1625MW195-0338-000-195-0338-000499OHM; DRAWING: @P2597_C02_LIB.P2597_C02(SCH_1):PAGE14; MAX_WATTAGE: 62.5mW; NO_XNET_CONNECTION: 1; NV_PN: 195-0338-000; PATH: I277; PHYS_PAGE: 14; ROT: 0; SEC: 1; SIGNAL_MODEL: nv_res; TOL: 1%; VER: 1; XY: (-7800,1400)
R583 = R: ASSEMBLY: HDMI; CDS_LIB: discrete; CDS_PART_NAME: R_0402-5.6OHM,5 %,62.5MW,195-0609-000; CDS_PHYS_PART_NAME: R_0402-5.6OHM,5 %,62.5MW,195-0609-000-195-0609-000,5.6OHM; CDS_SEC: 1; DEVICE_TYPENAME: R_0402-56OHM5625MW195-0609-000-195-0609-00056OHM; DRAWING: @P2597_C02_LIB.P2597_C02(SCH_1):PAGE14; MAX_WATTAGE: 62.5mW; NV_PN: 195-0609-000; PATH: I292; PHYS_PAGE: 14; PLACEMENT_NOTE: CoLayout with L506; ROT: 0; SEC: 1; SIGNAL_MODEL: nv_res; TOL: 5%; VER: 1; XY: (-4500,2750)
R584 = R: ASSEMBLY: HDMI; CDS_LIB: discrete; CDS_PART_NAME: R_0402-5.6OHM,5 %,62.5MW,195-0609-000; CDS_PHYS_PART_NAME: R_0402-5.6OHM,5 %,62.5MW,195-0609-000-195-0609-000,5.6OHM; CDS_SEC: 1; DEVICE_TYPENAME: R_0402-56OHM5625MW195-0609-000-195-0609-00056OHM; DRAWING: @P2597_C02_LIB.P2597_C02(SCH_1):PAGE14; MAX_WATTAGE: 62.5mW; NV_PN: 195-0609-000; PATH: I289; PHYS_PAGE: 14; PLACEMENT_NOTE: CoLayout with L506; ROT: 0; SEC: 1; SIGNAL_MODEL: nv_res; TOL: 5%; VER: 1; XY: (-4500,2400)
R586 = R: ASSEMBLY: HDMI; CDS_LIB: discrete; CDS_PART_NAME: R_0402-499OHM,1 %,62.5MW,195-0338-000; CDS_PHYS_PART_NAME: R_0402-499OHM,1 %,62.5MW,195-0338-000-195-0338-000,499OHM; CDS_SEC: 1; DEVICE_TYPENAME: R_0402-499OHM1625MW195-0338-000-195-0338-000499OHM; DRAWING: @P2597_C02_LIB.P2597_C02(SCH_1):PAGE14; MAX_WATTAGE: 62.5mW; NO_XNET_CONNECTION: 1; NV_PN: 195-0338-000; PATH: I276; PHYS_PAGE: 14; ROT: 0; SEC: 1; SIGNAL_MODEL: nv_res; TOL: 1%; VER: 1; XY: (-7800,1300)
R587 = R: ASSEMBLY: HDMI; CDS_LIB: discrete; CDS_PART_NAME: R_0402-32.4K,1 %,62.5MW,195-0250-000; CDS_PHYS_PART_NAME: R_0402-32.4K,1 %,62.5MW,195-0250-000-195-0250-000,32.4K; CDS_SEC: 1; DEVICE_TYPENAME: R_0402-324K1625MW195-0250-000-195-0250-000324K; DRAWING: @P2597_C02_LIB.P2597_C02(SCH_1):PAGE14; MAX_WATTAGE: 62.5mW; NV_PN: 195-0250-000; PATH: I290; PHYS_PAGE: 14; ROT: 2; SEC: 1; SIGNAL_MODEL: nv_res; TOL: 1%; VER: 1; XY: (-6000,4300)
R588 = R: ASSEMBLY: HDMI; CDS_LIB: discrete; CDS_PART_NAME: R_0402-162K,1 %,62.5MW,195-0106-000; CDS_PHYS_PART_NAME: R_0402-162K,1 %,62.5MW,195-0106-000-162K,195-0106-000; CDS_SEC: 1; DEVICE_TYPENAME: R_0402-162K1625MW195-0106-000-162K195-0106-000; DRAWING: @P2597_C02_LIB.P2597_C02(SCH_1):PAGE14; MAX_WATTAGE: 62.5mW; NV_PN: 195-0106-000; PATH: I311; PHYS_PAGE: 14; ROT: 2; SEC: 1; SIGNAL_MODEL: nv_res; TOL: 1%; VER: 1; XY: (-5350,5050)
U502 = U_POWER_SW#2: ASSEMBLY: HDMI; CDS_LIB: power_supply; CDS_PART_NAME: U_POWER_SW_DFN6-TPS2553DRVT-1,-9999V..9999V,-9999V..9999V,9999A,SWITCH,115-0619-000; CDS_PHYS_PART_NAME: U_POWER_SW_DFN6-TPS2553DRVT-1,-9999V..9999V,-9999V..9999V,9999A,SWITCH,115-0619-000-115-0619-000; CDS_SEC: 1; DEVICE_TYPENAME: U_POWER_SW_DFN6-TPS2553DRVT-1-9999V9999V-9999V9999V9999ASWITCH115-0619-000-115-0619-000; DRAWING: @P2597_C02_LIB.P2597_C02(SCH_1):PAGE14; FUNCTION: Power Switch; MAX_CURRENT: 9999A; MAX_VOLTAGE: -9999V..9999V; NV_NAME: TPS2553DRVT-1; NV_PN: 115-0619-000; OUTPUT_VOLTAGE: -9999V..9999V; PACK_TYPE: DFN6; PATH: I273; PHYS_PAGE: 14; ROT: 0; SEC: 1; SEC_TYPE: DFN6; TYPE: Switch; VER: 12; XY: (-8950,6250)

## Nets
5V0_HDMI_EN: R544.1 R548.1 R557.1 ; also on sheet 13
GND: C73.2 C74.2 C81.2 C82.2 C517.2 C520.2 C521.2 C522.2 C527.2 C528.2 D35.12(GND12) D35.14(GND14) D35.16(GND16) D35.18(GND18) D35.19(GND19) D35.21(GND21) J16.2(D2_SHIELD) J16.5(D1_SHIELD) J16.8(D0_SHIELD) J16.11(CK_SHIELD) J16.17(DDC_CEC_GND) J16.20(SHIELD1) J16.21(SHIELD2) J16.22(SHIELD3) J16.23(SHIELD4) Q505.2(S) Q507.2(E) R544.2 R550.2 R578.2 U502.5(GND) U502.7(GND2) ; also on sheet 1 2 3 4 5 6 7 9 10 11 12 13 14 15 16 17 18 19 21 22 23 24 25 26 30
VDD_1V8: R570.1 ; also on sheet 4 5 9 10 12 13 16 17 18 19 22 24 30
VDD_3V3_SLP: C517.1 Q508.1(G) R549.1 R558.1 R559.1 R560.1 R572.1 R573.1 R587.2 R588.1 ; also on sheet 4 5 11 16 17 21 22 25
VDD_5V0_HDMI: C81.1 C82.1 LB9.2 U502.6(VIN)
VDD_5V0_HDMI_CON: C73.1 C74.1 D35.17(LINE17) J16.18(5V) R561.1 R574.1 U502.1(VOUT)
VDD_5V0_IO_SYS: LB9.1 ; also on sheet 4 5 6 9 11 12 16 17 18 22 26 30
DDC_SCL_Q: Q506.5(G) R560.2
DDC_SDA_Q: Q506.2(G) R572.2
DP1_TXD0_N: C530.1 ; also on sheet 29
DP1_TXD0_P: C531.1 ; also on sheet 29
DP1_TXD1_N: C525.1 ; also on sheet 29
DP1_TXD1_P: C526.1 ; also on sheet 29
DP1_TXD2_N: C523.1 ; also on sheet 29
DP1_TXD2_P: C524.1 ; also on sheet 29
DP1_TXD3_N: C518.1 ; also on sheet 29
DP1_TXD3_P: C519.1 ; also on sheet 29
EN_HDMI_TERM: Q505.1(G) R557.2 R558.2
HDMI_CEC: CR501.1(A1) Q508.2(S) R588.2 ; also on sheet 29
HDMI_CEC_CON: C522.1 D35.13(LINE13) J16.13(CEC) L502.2
HDMI_CEC_PU: CR501.2(A2) R587.1
HDMI_CEC_Q: CR501.3(CC) L502.1 Q508.3(D)
HDMI_DDC_SCL_5V: Q506.3(D) R569.1 R574.2
HDMI_DDC_SCL_5V0: C521.1 D35.6(LINE6) J16.15(SCL) R569.2
HDMI_DDC_SCL_POL: Q506.4(S) R559.2 ; also on sheet 29
HDMI_DDC_SDA_5V: Q506.6(D) R561.2 R564.1
HDMI_DDC_SDA_5V0: C520.1 D35.15(LINE15) J16.16(SDA) R564.2
HDMI_DDC_SDA_POL: Q506.1(S) R573.2 ; also on sheet 29
HDMI_HPD: Q507.3(C) R570.2 ; also on sheet 29
HDMI_HPD_CON: C527.1 D35.3(LINE3) J16.19(HP_DET) L505.2
HDMI_HPD_L: C528.1 L505.1 R580.1
HDMI_HPD_R_L: Q507.1(B) R578.1 R580.2
HDMI_ILIM: R550.1 U502.2(ILIM)
HDMI_SW_EN: R547.1 R548.2 R549.2 U502.4(EN)
HDMI_SW_OC*: R547.2 U502.3(FAULT*)
HDMI_TXC_C_N: C518.2 L501.1 R562.2 R563.1
HDMI_TXC_C_P: C519.2 L501.2 R565.1 R566.2
HDMI_TXC_CON_N: D35.1(LINE1) J16.12(CK*) L501.4 R563.2
HDMI_TXC_CON_P: D35.2(LINE2) J16.10(CK) L501.3 R565.2
HDMI_TXD0_C_N: C523.2 L503.1 R567.2 R568.1
HDMI_TXD0_C_P: C524.2 L503.2 R571.1 R575.2
HDMI_TXD0_CON_N: D35.4(LINE4) J16.9(D0*) L503.4 R568.2
HDMI_TXD0_CON_P: D35.5(LINE5) J16.7(D0) L503.3 R571.2
HDMI_TXD1_C_N: C525.2 L504.1 R576.2 R577.1
HDMI_TXD1_C_P: C526.2 L504.2 R579.1 R581.2
HDMI_TXD1_CON_N: D35.7(LINE7) J16.6(D1*) L504.4 R577.2
HDMI_TXD1_CON_P: D35.8(LINE8) J16.4(D1) L504.3 R579.2
HDMI_TXD2_C_N: C530.2 L506.1 R582.2 R583.1
HDMI_TXD2_C_P: C531.2 L506.2 R584.1 R586.2
HDMI_TXD2_CON_N: D35.10(LINE10) J16.3(D2*) L506.4 R583.2
HDMI_TXD2_CON_P: D35.11(LINE11) J16.1(D2) L506.3 R584.2
IFP_TERM_EN: LB1.1 LB2.1 LB3.1 LB4.1 LB5.1 LB6.1 LB7.1 LB8.1 Q505.3(D)
IFP_TERM_EN_TXCN: LB8.2 R562.1
IFP_TERM_EN_TXCP: LB7.2 R566.1
IFP_TERM_EN_TXD0N: LB6.2 R567.1
IFP_TERM_EN_TXD0P: LB5.2 R575.1
IFP_TERM_EN_TXD1N: LB4.2 R576.1
IFP_TERM_EN_TXD1P: LB3.2 R581.1
IFP_TERM_EN_TXD2N: LB2.2 R582.1
IFP_TERM_EN_TXD2P: LB1.2 R586.1
SNN_D35_9: D35.9(LINE9)
SNN_D35_20: D35.20(GND20)
SNN_HDMI_RES: J16.14(RESERVED)

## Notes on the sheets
sheet 20
- A
- B
- C
- D
- E
- F
- G
- H
- HDMI Connector
- 1
- 1
- MINIMUM 200MA
- FOR HDMI TO VGA
- DONGLE
- 2
- 2
- DIFFPAIR
- NV_NETCLASS
- PCB CO-LAYOUT
- 3
- 3
- NV_NETCLASS
- DIFFPAIR
- 4
- 4
- HDMI ESD, CLOSE TO INPUT CONNECTOR
- 5
- 5
- NVIDIA CORPORATION
- 2701 SAN TOMAS EXPRESSWAY
- ASSEMBLY
- <ASSEMBLY_DESCRIPTION>
- SANTA CLARA, CA 95050, USA
- PAGE DETAIL
- HDMI
- NV_PN
- 600-82597-BASE-900
- ALL NVIDIA DESIGN SPECIFICATIONS, REFERENCE SPECIFICATIONS, REFERENCE BOARDS, FILES, DRAWINGS, DIAGNOSTICS, LISTS AND OTHER DOCUMENTS OR INFORMATION (TOGETHER AND SEPARATELY, 'MATERIALS') ARE BEING PROVIDED 'AS IS'. THE MATERIALS MAY
- CONTAIN KNOWN AND UNKNOWN VIOLATIONS OR DEVIATIONS OF INDUSTRY STANDARDS AND SPECIFICATIONS. NVIDIA MAKES NO WARRANTIES, EXPRESSED, IMPLIED, STATUTORY OR OTHERWISE WITH RESPECT TO THE MATERIALS OR OTHERWISE, AND EXPRESSLY DISCLAIMS ALL
- PCB REV
- P2597-C02
- PAGE
- 14 OF 34
- IMPLIED WARRANTIES INCLUDING, WITHOUT LIMITATION, THE WARRANTIES OF DESIGN, OF NONINFRINGEMENT, MERCHANTABILITY OR FITNESS FOR A PARTICULAR PURPOSE, OR ARISING FROM A COURSE OF DEALING, TRADE USAGE, TRADE PRACTICE, OR INDUSTRY STANDARDS.
- BOM REV
- A
- DATE
- 23-OCT-2017
- A
- B
- C
- D
- E
- F
- G
- H
